Omron CX-Programmer project NuevoProyecto (CX-Programmer 9.50)

# PLC NewPLC1: CP1L-E EM

## Program P1_2 (cyclic task 0)
Local symbols
B 100.00 BOOL
Etapa_0 10.00 BOOL
Etapa_1 10.01 BOOL
FSp 15.00 BOOL  ; Flanco de Subida de p
p 0.00 BOOL

### Section Sección1_Programa_principal
; Programa principal (Etapa 0 y Etapa 1)

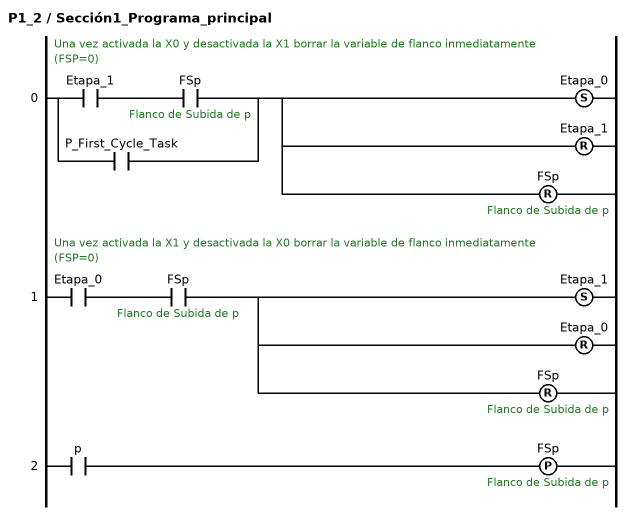
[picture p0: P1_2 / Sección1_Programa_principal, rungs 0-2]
; rung 0: Una vez activada la X0 y desactivada la X1 borrar la variable de flanco inmediatamente (FSP=0)
LD Etapa_1
AND FSp  ; Flanco de Subida de p
OR P_First_Cycle_Task
SET Etapa_0
RSET Etapa_1
RSET FSp  ; Flanco de Subida de p
; rung 1: Una vez activada la X1 y desactivada la X0 borrar la variable de flanco inmediatamente (FSP=0)
LD Etapa_0
AND FSp  ; Flanco de Subida de p
SET Etapa_1
RSET Etapa_0
RSET FSp  ; Flanco de Subida de p
; rung 2
LD p
DIFU(013) FSp  ; Flanco de Subida de p

### Section Sección2_Salida

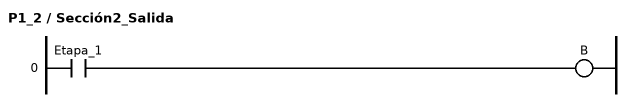
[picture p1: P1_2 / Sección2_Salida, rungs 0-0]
; rung 0
LD Etapa_1
OUT B

### Section Sección3_END
; rung 0
END(001)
